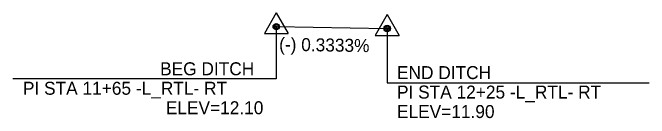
# Model space of a CAD drawing. Extents: x 2179808 to 2190174, y 63168 to 78602.
# Drawn here: x 2179963.2 to 2180307.9, y 63168.4 to 63225.3 of the extents above; entities that cross this region are included whole.
import ezdxf

# ---------------------------------------------------------------- set-up
doc = ezdxf.new("R2010")
doc.units = 0
for name, color, linetype in [('Default', 7, 'Continuous'), ('Prop Vertical Profile Ditch Grade Right', 7, 'Continuous'), ('Prop Vertical Profile Ditch Grade Right Label', 7, 'Continuous'), ('Prop VPI Ditch Grade Right Label', 7, 'Continuous')]:
    doc.layers.add(name, color=color, linetype=linetype)

msp = doc.modelspace()

# ---------------------------------------------------------------- linework, layer by layer
at = {"layer": 'Default'}
for p, q in [((2180105.9, 63225.26), (2180099.45, 63214.06)), ((2180105.9, 63225.26), (2180112.4, 63214.06)), ((2180165.9, 63224.26), (2180159.45, 63213.06)), ((2180165.9, 63224.26), (2180172.4, 63213.06)), ((2180099.45, 63214.06), (2180112.4, 63214.06)), ((2180159.45, 63213.06), (2180172.4, 63213.06))]:
    msp.add_line(p, q, dxfattribs=at)
for centre, radius in [((2180105.9, 63217.78), 1.75), ((2180105.9, 63217.78), 1.2), ((2180165.9, 63216.78), 1.75), ((2180165.9, 63216.78), 1.2)]:
    msp.add_circle(centre, radius, dxfattribs=at)
at = {"layer": 'Prop Vertical Profile Ditch Grade Right'}
msp.add_line((2180105.9, 63217.78), (2180165.9, 63216.78), dxfattribs=at)
at = {"layer": 'Prop VPI Ditch Grade Right Label'}
for points in [[(2180105.9, 63217.78), (2180105.9, 63189.57), (2179963.19, 63189.57)], [(2180165.9, 63216.78), (2180165.9, 63187.51), (2180307.85, 63187.51)]]:
    msp.add_lwpolyline(points, dxfattribs=at)
for centre in [(2180105.9, 63217.78), (2180165.9, 63216.78)]:
    msp.add_circle(centre, 0.5, dxfattribs=at)

# ---------------------------------------------------------------- texts
at = {"layer": 'Prop Vertical Profile Ditch Grade Right Label'}
msp.add_text('(-) 0.3333%', height=7, rotation=359.0452, dxfattribs=at).set_placement((2180107.4, 63204.84))
at = {"layer": 'Prop VPI Ditch Grade Right Label'}
for s, p in [('BEG DITCH', (2180042.99, 63191.57)), ('END DITCH', (2180171.25, 63189.51)), ('PI STA 11+65 -L_RTL- RT', (2179968.71, 63181.07)), ('PI STA 12+25 -L_RTL- RT', (2180171.25, 63179.01)), ('ELEV=12.10', (2180046.08, 63170.57)), ('ELEV=11.90', (2180171.25, 63168.51))]:
    msp.add_text(s, height=7, dxfattribs=at).set_placement(p)

doc.saveas('drawing.dxf')
